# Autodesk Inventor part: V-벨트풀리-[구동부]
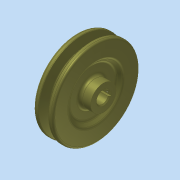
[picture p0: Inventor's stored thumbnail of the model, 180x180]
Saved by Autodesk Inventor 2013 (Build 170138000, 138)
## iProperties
Company: 한국ATC센터
Created: 2014-02
Part Number: V-벨트풀리-[구동부]
Document SubType Name: Modeling
Designer: KYOUNG IL JANG
Density: 7.25 g/cm^3
Mass: 594.643 g
Surface Area: 210.328 cm^2
Volume: 82.0197 cm^3
Material: 주철
Vendor: CBT Solutions
Author: KYOUNG IL JANG
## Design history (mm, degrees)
sketch "스케치1"
  geometry: L1 (-13, 0)-(13, 0); L2 (-13, 0)-(-13, 12.5); L3 (-13, 12.5)-(-9, 12.5); L4 (-9, 12.5)-(-9, 23); L5 (-9, 23)-(-13, 27); L6 (-13, 27)-(-13, 42.7); L7 (-13, 42.7)-(-8.325, 42.7); L8 (-8.325, 42.7)-(-5.574, 33.7); L9 (-5.574, 33.7)-(-1.426, 33.7); L10 (-1.426, 33.7)-(1.325, 42.7); L11 (1.325, 42.7)-(6, 42.7); L12 (6, 42.7)-(6, 27); L13 (6, 27)-(2, 23); L14 (2, 23)-(2, 12.5); L15 (2, 12.5)-(13, 12.5); L16 (13, 12.5)-(13, 0); L17 (-7.5, 40)-(0.5, 40); 2 further points
  constraints: 34 end point, 6 parallel, 5 collinear, 5 equal length, 4 perpendicular, 2 point on line, 1 coincident, 1 horizontal, 1 midpoint
  dimensions: "d0" = 26 distance of L1.start L1.end; "d1" = 2.7 distance between parallel lines of L7 L17; "d2" = 6.3 distance between parallel lines of L9 L17; "d3" = 8 distance of L17.start L17.end; "d4" = 34 deg angle of L10 L8; "d5" = 19 distance between parallel lines of L12 L6; "d7" = 25 diameter of L15 L1; "d8" = 46 diameter of L13.end L1; "d9" = 54 diameter of L12.end L1; "d10" = 4 distance between parallel lines of L2 L4; "d11" = 80 diameter of L17 L1
revolve "회전1" sketch "스케치1" stored, may be unused: angle "d12" = 90 deg
sketch "스케치2"
  geometry: L1 (-2, 5.657)-(-2, 7.8); L2 (-2, 7.8)-(2, 7.8); L3 (2, 7.8)-(2, 5.657); A1 r 6 centre (0, 0) between (-2, 5.657) and (2, 5.657); 1 further point
  constraints: 6 end point, 2 parallel, 2 point on circle, 1 centre point, 1 coincident, 1 perpendicular, 1 vertical
  dimensions: "d13" = 12 diameter of A1; "d14" = 13.8 dimension on A1 L2; "d15" = 4 distance of L1.end L2.end
extrude "돌출1" cut sketch "스케치2" stored distance "d16" = 10; taper "d17" = 0 deg
node "작업 평면1"
sketch "스케치3"
  geometry: L1 (-5.5, 12.5)-(-5.5, -12.5) reference; 3 further points
  constraints: 1 horizontal alignment, 1 midpoint
  dimensions: "d18" = 4 distance from line of point (-1.5, 0) L1
hole "구멍1" sketch "스케치3" at (-1.5, 0) diameter "d19" = 2.459; stored, may be unused: countersink angle "d23" = 90 deg, drill point angle "d25" = 118 deg; dims "d20" = 6, "d21" = 4, "d22" = 2, "d24" = 8
fillet "모깎기1" dims "d26" = 2, "d27" = 0.5, "d28" = 1, "d29" = 3
chamfer "모따기1" distance "d30" = 1; stored, may be unused: second distance "d31" = 2, angle "d32" = 45 deg
node "솔리드1"
